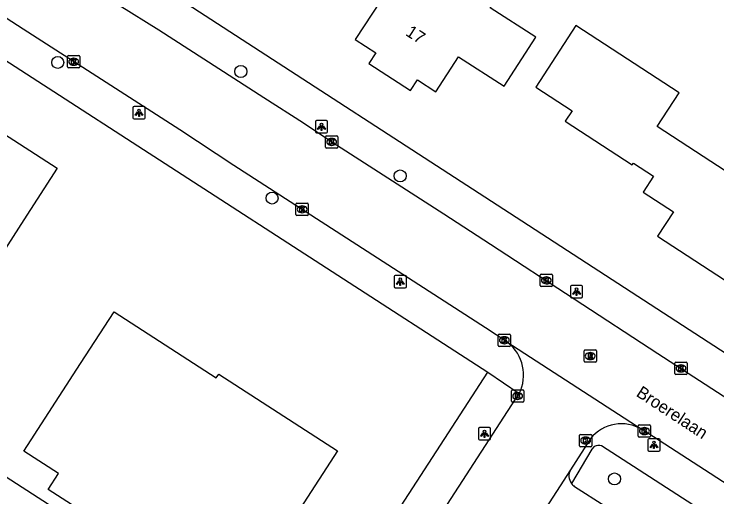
# Model space of a CAD drawing. Extents: x 161141 to 161601, y 381708 to 382245.
# Drawn here: x 161459.7 to 161516.9, y 382033 to 382072.3 of the extents above; entities that cross this region are included whole.
import ezdxf

# ---------------------------------------------------------------- set-up
doc = ezdxf.new("R2010")
doc.units = 0
for name, color, linetype in [('IMGEO_Boom', 7, 'Continuous'), ('IMGEO_Kolk', 7, 'Continuous'), ('IMGEO_Lichtpunt', 7, 'Continuous'), ('IMGEO_Openbare_ruimte_label', 7, 'Continuous'), ('IMGEO_Pand', 7, 'Continuous'), ('IMGEO_Pand_nummerreeks', 7, 'Continuous'), ('IMGEO_Parkeervlak_open', 7, 'Continuous'), ('IMGEO_Rijbaan_lokaal_open', 7, 'Continuous'), ('IMGEO_Rioolput', 7, 'Continuous'), ('IMGEO_Voetpad_open', 7, 'Continuous')]:
    doc.layers.add(name, color=color, linetype=linetype)

msp = doc.modelspace()

# ---------------------------------------------------------------- linework, layer by layer
at = {"layer": 'IMGEO_Boom'}
for centre in [(161463.28, 382068.331), (161478.171, 382067.593), (161491.119, 382059.095), (161480.703, 382057.296), (161508.547, 382034.432)]:
    msp.add_circle(centre, 0.489, dxfattribs=at)
at = {"layer": 'IMGEO_Kolk'}
for p, q in [((161464.08, 382067.96), (161464.08, 382068.812)), ((161464.155, 382068.886), (161465.007, 382068.886)), ((161465.081, 382068.812), (161465.081, 382067.96)), ((161464.591, 382068.106), (161464.566, 382068.106)), ((161464.568, 382068.666), (161464.593, 382068.666)), ((161465.007, 382067.886), (161464.155, 382067.886)), ((161485.053, 382061.434), (161485.053, 382062.286)), ((161485.128, 382062.36), (161485.98, 382062.36)), ((161485.541, 382062.14), (161485.566, 382062.14)), ((161486.054, 382062.286), (161486.054, 382061.434)), ((161485.98, 382061.36), (161485.128, 382061.36)), ((161485.564, 382061.58), (161485.539, 382061.58)), ((161482.65, 382055.951), (161482.65, 382056.803)), ((161482.725, 382056.877), (161483.577, 382056.877)), ((161483.651, 382056.803), (161483.651, 382055.951)), ((161483.138, 382056.657), (161483.163, 382056.657)), ((161483.577, 382055.877), (161482.725, 382055.877)), ((161483.161, 382056.097), (161483.136, 382056.097)), ((161502.507, 382050.171), (161502.507, 382051.023)), ((161502.582, 382051.097), (161503.434, 382051.097)), ((161503.508, 382051.023), (161503.508, 382050.171)), ((161502.995, 382050.877), (161503.02, 382050.877)), ((161503.434, 382050.097), (161502.582, 382050.097)), ((161503.018, 382050.317), (161502.993, 382050.317)), ((161499.094, 382045.296), (161499.094, 382046.148)), ((161499.169, 382046.222), (161500.021, 382046.222)), ((161499.582, 382046.002), (161499.607, 382046.002)), ((161500.095, 382046.148), (161500.095, 382045.296)), ((161499.605, 382045.442), (161499.58, 382045.442)), ((161500.021, 382045.222), (161499.169, 382045.222)), ((161513.457, 382043.004), (161513.457, 382043.856)), ((161513.532, 382043.93), (161514.384, 382043.93)), ((161513.945, 382043.71), (161513.97, 382043.71)), ((161514.458, 382043.856), (161514.458, 382043.004)), ((161513.968, 382043.15), (161513.943, 382043.15)), ((161514.384, 382042.93), (161513.532, 382042.93)), ((161500.17, 382040.761), (161500.17, 382041.613)), ((161500.245, 382041.687), (161501.097, 382041.687)), ((161500.658, 382041.467), (161500.683, 382041.467)), ((161501.171, 382041.613), (161501.171, 382040.761)), ((161501.097, 382040.687), (161500.245, 382040.687)), ((161500.681, 382040.907), (161500.656, 382040.907)), ((161510.478, 382037.909), (161510.478, 382038.761)), ((161510.553, 382038.835), (161511.405, 382038.835)), ((161510.966, 382038.615), (161510.991, 382038.615)), ((161511.479, 382038.761), (161511.479, 382037.909)), ((161505.697, 382037.134), (161505.697, 382037.986)), ((161505.772, 382038.06), (161506.624, 382038.06)), ((161506.185, 382037.84), (161506.21, 382037.84)), ((161506.698, 382037.986), (161506.698, 382037.134)), ((161511.405, 382037.835), (161510.553, 382037.835)), ((161510.989, 382038.055), (161510.964, 382038.055)), ((161506.208, 382037.28), (161506.183, 382037.28)), ((161506.624, 382037.06), (161505.772, 382037.06))]:
    msp.add_line(p, q, dxfattribs=at)
for points in [[(161464.08, 382067.96), (161464.08, 382068.812)], [(161464.155, 382068.886), (161465.007, 382068.886)], [(161465.081, 382068.812), (161465.081, 382067.96)], [(161464.401, 382068.586), (161464.524, 382068.586), (161464.524, 382068.435), (161464.654, 382068.586), (161464.818, 382068.586), (161464.672, 382068.435), (161464.825, 382068.186), (161464.673, 382068.186), (161464.588, 382068.35), (161464.524, 382068.283), (161464.524, 382068.186), (161464.401, 382068.186), (161464.401, 382068.586)], [(161465.007, 382067.886), (161464.155, 382067.886)], [(161485.053, 382061.434), (161485.053, 382062.286)], [(161485.128, 382062.36), (161485.98, 382062.36)], [(161485.374, 382062.06), (161485.497, 382062.06), (161485.497, 382061.909), (161485.627, 382062.06), (161485.791, 382062.06), (161485.645, 382061.909), (161485.798, 382061.66), (161485.646, 382061.66), (161485.561, 382061.824), (161485.497, 382061.757), (161485.497, 382061.66), (161485.374, 382061.66), (161485.374, 382062.06)], [(161486.054, 382062.286), (161486.054, 382061.434)], [(161485.98, 382061.36), (161485.128, 382061.36)], [(161482.65, 382055.951), (161482.65, 382056.803)], [(161482.725, 382056.877), (161483.577, 382056.877)], [(161483.651, 382056.803), (161483.651, 382055.951)], [(161482.971, 382056.577), (161483.094, 382056.577), (161483.094, 382056.426), (161483.224, 382056.577), (161483.388, 382056.577), (161483.242, 382056.426), (161483.395, 382056.177), (161483.243, 382056.177), (161483.158, 382056.341), (161483.094, 382056.274), (161483.094, 382056.177), (161482.971, 382056.177), (161482.971, 382056.577)], [(161483.577, 382055.877), (161482.725, 382055.877)], [(161502.507, 382050.171), (161502.507, 382051.023)], [(161502.582, 382051.097), (161503.434, 382051.097)], [(161503.508, 382051.023), (161503.508, 382050.171)], [(161502.828, 382050.797), (161502.951, 382050.797), (161502.951, 382050.646), (161503.081, 382050.797), (161503.245, 382050.797), (161503.099, 382050.646), (161503.252, 382050.397), (161503.1, 382050.397), (161503.015, 382050.561), (161502.951, 382050.494), (161502.951, 382050.397), (161502.828, 382050.397), (161502.828, 382050.797)], [(161503.434, 382050.097), (161502.582, 382050.097)], [(161499.094, 382045.296), (161499.094, 382046.148)], [(161499.169, 382046.222), (161500.021, 382046.222)], [(161499.415, 382045.922), (161499.538, 382045.922), (161499.538, 382045.771), (161499.668, 382045.922), (161499.832, 382045.922), (161499.686, 382045.771), (161499.839, 382045.522), (161499.687, 382045.522), (161499.602, 382045.686), (161499.538, 382045.619), (161499.538, 382045.522), (161499.415, 382045.522), (161499.415, 382045.922)], [(161500.095, 382046.148), (161500.095, 382045.296)], [(161500.021, 382045.222), (161499.169, 382045.222)], [(161513.457, 382043.004), (161513.457, 382043.856)], [(161513.532, 382043.93), (161514.384, 382043.93)], [(161513.778, 382043.63), (161513.901, 382043.63), (161513.901, 382043.479), (161514.031, 382043.63), (161514.195, 382043.63), (161514.049, 382043.479), (161514.202, 382043.23), (161514.05, 382043.23), (161513.965, 382043.394), (161513.901, 382043.327), (161513.901, 382043.23), (161513.778, 382043.23), (161513.778, 382043.63)], [(161514.458, 382043.856), (161514.458, 382043.004)], [(161514.384, 382042.93), (161513.532, 382042.93)], [(161500.17, 382040.761), (161500.17, 382041.613)], [(161500.245, 382041.687), (161501.097, 382041.687)], [(161500.491, 382041.387), (161500.614, 382041.387), (161500.614, 382041.236), (161500.744, 382041.387), (161500.908, 382041.387), (161500.762, 382041.236), (161500.915, 382040.987), (161500.763, 382040.987), (161500.678, 382041.151), (161500.614, 382041.084), (161500.614, 382040.987), (161500.491, 382040.987), (161500.491, 382041.387)], [(161501.171, 382041.613), (161501.171, 382040.761)], [(161501.097, 382040.687), (161500.245, 382040.687)], [(161510.478, 382037.909), (161510.478, 382038.761)], [(161510.553, 382038.835), (161511.405, 382038.835)], [(161510.799, 382038.535), (161510.922, 382038.535), (161510.922, 382038.384), (161511.052, 382038.535), (161511.216, 382038.535), (161511.07, 382038.384), (161511.223, 382038.135), (161511.071, 382038.135), (161510.986, 382038.299), (161510.922, 382038.232), (161510.922, 382038.135), (161510.799, 382038.135), (161510.799, 382038.535)], [(161511.479, 382038.761), (161511.479, 382037.909)], [(161505.697, 382037.134), (161505.697, 382037.986)], [(161505.772, 382038.06), (161506.624, 382038.06)], [(161506.698, 382037.986), (161506.698, 382037.134)], [(161511.405, 382037.835), (161510.553, 382037.835)], [(161506.018, 382037.76), (161506.141, 382037.76), (161506.141, 382037.609), (161506.271, 382037.76), (161506.435, 382037.76), (161506.289, 382037.609), (161506.442, 382037.36), (161506.29, 382037.36), (161506.205, 382037.524), (161506.141, 382037.457), (161506.141, 382037.36), (161506.018, 382037.36), (161506.018, 382037.76)], [(161506.624, 382037.06), (161505.772, 382037.06)]]:
    msp.add_lwpolyline(points, dxfattribs=at)
for centre, start, end in [((161464.157, 382068.81), 91.552, 178.448), ((161464.157, 382068.81), 91.552, 178.448), ((161465.005, 382068.81), 1.552, 88.448), ((161465.005, 382068.81), 1.552, 88.448), ((161464.157, 382067.962), 181.552, 268.448), ((161464.157, 382067.962), 181.552, 268.448), ((161465.005, 382067.962), 271.552, 358.448), ((161465.005, 382067.962), 271.552, 358.448), ((161485.13, 382062.284), 91.552, 178.448), ((161485.13, 382062.284), 91.552, 178.448), ((161485.978, 382062.284), 1.552, 88.448), ((161485.978, 382062.284), 1.552, 88.448), ((161485.13, 382061.436), 181.552, 268.448), ((161485.13, 382061.436), 181.552, 268.448), ((161485.978, 382061.436), 271.552, 358.448), ((161485.978, 382061.436), 271.552, 358.448), ((161482.727, 382056.801), 91.552, 178.448), ((161482.727, 382056.801), 91.552, 178.448), ((161483.575, 382056.801), 1.552, 88.448), ((161483.575, 382056.801), 1.552, 88.448), ((161482.727, 382055.953), 181.552, 268.448), ((161482.727, 382055.953), 181.552, 268.448), ((161483.575, 382055.953), 271.552, 358.448), ((161483.575, 382055.953), 271.552, 358.448), ((161502.584, 382051.021), 91.552, 178.448), ((161502.584, 382051.021), 91.552, 178.448), ((161503.432, 382051.021), 1.552, 88.448), ((161503.432, 382051.021), 1.552, 88.448), ((161502.584, 382050.173), 181.552, 268.448), ((161502.584, 382050.173), 181.552, 268.448), ((161503.432, 382050.173), 271.552, 358.448), ((161503.432, 382050.173), 271.552, 358.448), ((161499.171, 382046.146), 91.552, 178.448), ((161499.171, 382046.146), 91.552, 178.448), ((161500.019, 382046.146), 1.552, 88.448), ((161500.019, 382046.146), 1.552, 88.448), ((161499.171, 382045.298), 181.552, 268.448), ((161499.171, 382045.298), 181.552, 268.448), ((161500.019, 382045.298), 271.552, 358.448), ((161500.019, 382045.298), 271.552, 358.448), ((161513.534, 382043.854), 91.552, 178.448), ((161513.534, 382043.854), 91.552, 178.448), ((161514.382, 382043.854), 1.552, 88.448), ((161514.382, 382043.854), 1.552, 88.448), ((161513.534, 382043.006), 181.552, 268.448), ((161513.534, 382043.006), 181.552, 268.448), ((161514.382, 382043.006), 271.552, 358.448), ((161514.382, 382043.006), 271.552, 358.448), ((161500.247, 382041.611), 91.552, 178.448), ((161500.247, 382041.611), 91.552, 178.448), ((161501.095, 382041.611), 1.552, 88.448), ((161501.095, 382041.611), 1.552, 88.448), ((161500.247, 382040.763), 181.552, 268.448), ((161500.247, 382040.763), 181.552, 268.448), ((161501.095, 382040.763), 271.552, 358.448), ((161501.095, 382040.763), 271.552, 358.448), ((161510.555, 382038.759), 91.552, 178.448), ((161510.555, 382038.759), 91.552, 178.448), ((161511.403, 382038.759), 1.552, 88.448), ((161511.403, 382038.759), 1.552, 88.448), ((161505.774, 382037.984), 91.552, 178.448), ((161505.774, 382037.984), 91.552, 178.448), ((161506.622, 382037.984), 1.552, 88.448), ((161506.622, 382037.984), 1.552, 88.448), ((161510.555, 382037.911), 181.552, 268.448), ((161510.555, 382037.911), 181.552, 268.448), ((161511.403, 382037.911), 271.552, 358.448), ((161511.403, 382037.911), 271.552, 358.448), ((161505.774, 382037.136), 181.552, 268.448), ((161505.774, 382037.136), 181.552, 268.448), ((161506.622, 382037.136), 271.552, 358.448), ((161506.622, 382037.136), 271.552, 358.448)]:
    msp.add_arc(centre, 0.0765, start, end, dxfattribs=at)
for centre, major_axis, ratio, start_param, end_param in [((161464.567, 382068.386), (-0.387, 0.002), 0.722429, 4.712389, 7.853982), ((161464.592, 382068.386), (-0.39, 0.002), 0.717154, 1.570796, 4.712389), ((161485.54, 382061.86), (-0.387, 0.002), 0.722429, 4.712389, 7.853982), ((161485.565, 382061.86), (-0.39, 0.002), 0.717154, 1.570796, 4.712389), ((161483.137, 382056.377), (-0.387, 0.002), 0.722429, 4.712389, 7.853982), ((161483.162, 382056.377), (-0.39, 0.002), 0.717154, 1.570796, 4.712389), ((161502.994, 382050.597), (-0.387, 0.002), 0.722429, 4.712389, 7.853982), ((161503.019, 382050.597), (-0.39, 0.002), 0.717154, 1.570796, 4.712389), ((161499.581, 382045.722), (-0.387, 0.002), 0.722429, 4.712389, 7.853982), ((161499.606, 382045.722), (-0.39, 0.002), 0.717154, 1.570796, 4.712389), ((161513.944, 382043.43), (-0.387, 0.002), 0.722429, 4.712389, 7.853982), ((161513.969, 382043.43), (-0.39, 0.002), 0.717154, 1.570796, 4.712389), ((161500.657, 382041.187), (-0.387, 0.002), 0.722429, 4.712389, 7.853982), ((161500.682, 382041.187), (-0.39, 0.002), 0.717154, 1.570796, 4.712389), ((161510.965, 382038.335), (-0.387, 0.002), 0.722429, 4.712389, 7.853982), ((161510.99, 382038.335), (-0.39, 0.002), 0.717154, 1.570796, 4.712389), ((161506.184, 382037.56), (-0.387, 0.002), 0.722429, 4.712389, 7.853982), ((161506.209, 382037.56), (-0.39, 0.002), 0.717154, 1.570796, 4.712389)]:
    msp.add_ellipse(centre, major_axis=major_axis, ratio=ratio, start_param=start_param, end_param=end_param, dxfattribs=at)
at = {"layer": 'IMGEO_Lichtpunt'}
for p, q in [((161470.297, 382064.733), (161469.489, 382064.733)), ((161470.297, 382064.733), (161469.489, 382064.733)), ((161469.395, 382064.638), (161469.395, 382063.831)), ((161469.395, 382064.638), (161469.395, 382063.831)), ((161470.391, 382063.831), (161470.391, 382064.638)), ((161470.391, 382063.831), (161470.391, 382064.638)), ((161469.489, 382063.737), (161470.297, 382063.737)), ((161469.489, 382063.737), (161470.297, 382063.737)), ((161485.129, 382063.595), (161484.321, 382063.595)), ((161485.129, 382063.595), (161484.321, 382063.595)), ((161484.227, 382063.5), (161484.227, 382062.693)), ((161484.227, 382063.5), (161484.227, 382062.693)), ((161485.223, 382062.693), (161485.223, 382063.5)), ((161485.223, 382062.693), (161485.223, 382063.5)), ((161484.321, 382062.599), (161485.129, 382062.599)), ((161484.321, 382062.599), (161485.129, 382062.599)), ((161491.534, 382050.992), (161490.726, 382050.992)), ((161491.534, 382050.992), (161490.726, 382050.992)), ((161490.632, 382050.897), (161490.632, 382050.09)), ((161490.632, 382050.897), (161490.632, 382050.09)), ((161491.628, 382050.09), (161491.628, 382050.897)), ((161491.628, 382050.09), (161491.628, 382050.897)), ((161490.726, 382049.996), (161491.534, 382049.996)), ((161490.726, 382049.996), (161491.534, 382049.996)), ((161504.962, 382050.083), (161504.962, 382049.276)), ((161504.962, 382050.083), (161504.962, 382049.276)), ((161505.864, 382050.178), (161505.056, 382050.178)), ((161505.864, 382050.178), (161505.056, 382050.178)), ((161505.958, 382049.276), (161505.958, 382050.083)), ((161505.958, 382049.276), (161505.958, 382050.083)), ((161505.056, 382049.182), (161505.864, 382049.182)), ((161505.056, 382049.182), (161505.864, 382049.182)), ((161497.481, 382038.515), (161497.481, 382037.708)), ((161497.481, 382038.515), (161497.481, 382037.708)), ((161498.383, 382038.61), (161497.575, 382038.61)), ((161498.383, 382038.61), (161497.575, 382038.61)), ((161498.477, 382037.708), (161498.477, 382038.515)), ((161498.477, 382037.708), (161498.477, 382038.515)), ((161497.575, 382037.614), (161498.383, 382037.614)), ((161497.575, 382037.614), (161498.383, 382037.614)), ((161511.254, 382037.606), (161511.254, 382036.799)), ((161511.254, 382037.606), (161511.254, 382036.799)), ((161512.156, 382037.701), (161511.348, 382037.701)), ((161512.156, 382037.701), (161511.348, 382037.701)), ((161512.25, 382036.799), (161512.25, 382037.606)), ((161512.25, 382036.799), (161512.25, 382037.606)), ((161511.348, 382036.705), (161512.156, 382036.705)), ((161511.348, 382036.705), (161512.156, 382036.705))]:
    msp.add_line(p, q, dxfattribs=at)
for points in [[(161469.769, 382064.302), (161469.808, 382064.274), (161469.62, 382064.012), (161469.582, 382064.039), (161469.769, 382064.302)], [(161469.871, 382064.254), (161469.918, 382064.254), (161469.918, 382063.932), (161469.871, 382063.932), (161469.871, 382064.254)], [(161469.981, 382064.274), (161470.019, 382064.301), (161470.206, 382064.039), (161470.167, 382064.011), (161469.981, 382064.274)], [(161484.601, 382063.164), (161484.64, 382063.136), (161484.452, 382062.874), (161484.414, 382062.901), (161484.601, 382063.164)], [(161484.703, 382063.116), (161484.75, 382063.116), (161484.75, 382062.794), (161484.703, 382062.794), (161484.703, 382063.116)], [(161484.813, 382063.136), (161484.851, 382063.163), (161485.038, 382062.901), (161484.999, 382062.873), (161484.813, 382063.136)], [(161491.006, 382050.561), (161491.045, 382050.533), (161490.857, 382050.271), (161490.819, 382050.298), (161491.006, 382050.561)], [(161491.108, 382050.513), (161491.155, 382050.513), (161491.155, 382050.191), (161491.108, 382050.191), (161491.108, 382050.513)], [(161491.218, 382050.533), (161491.256, 382050.56), (161491.443, 382050.298), (161491.404, 382050.27), (161491.218, 382050.533)], [(161505.336, 382049.747), (161505.375, 382049.719), (161505.187, 382049.457), (161505.149, 382049.484), (161505.336, 382049.747)], [(161505.438, 382049.699), (161505.485, 382049.699), (161505.485, 382049.377), (161505.438, 382049.377), (161505.438, 382049.699)], [(161505.548, 382049.719), (161505.586, 382049.746), (161505.773, 382049.484), (161505.734, 382049.456), (161505.548, 382049.719)], [(161497.855, 382038.179), (161497.894, 382038.151), (161497.706, 382037.889), (161497.668, 382037.916), (161497.855, 382038.179)], [(161497.957, 382038.131), (161498.004, 382038.131), (161498.004, 382037.809), (161497.957, 382037.809), (161497.957, 382038.131)], [(161498.067, 382038.151), (161498.105, 382038.178), (161498.292, 382037.916), (161498.253, 382037.888), (161498.067, 382038.151)], [(161511.628, 382037.27), (161511.667, 382037.242), (161511.479, 382036.98), (161511.441, 382037.007), (161511.628, 382037.27)], [(161511.84, 382037.242), (161511.878, 382037.269), (161512.065, 382037.007), (161512.026, 382036.979), (161511.84, 382037.242)], [(161511.73, 382037.222), (161511.777, 382037.222), (161511.777, 382036.9), (161511.73, 382036.9), (161511.73, 382037.222)]]:
    msp.add_lwpolyline(points, dxfattribs=at)
for centre in [(161469.894, 382064.436), (161484.726, 382063.298), (161491.131, 382050.695), (161505.461, 382049.881), (161497.98, 382038.313), (161511.753, 382037.404)]:
    msp.add_circle(centre, 0.0994, dxfattribs=at)
for centre, start, end in [((161469.489, 382064.638), 90, 180), ((161469.489, 382064.638), 90, 180), ((161470.297, 382064.638), 0, 90), ((161470.297, 382064.638), 0, 90), ((161469.489, 382063.831), 180, 270), ((161469.489, 382063.831), 180, 270), ((161470.297, 382063.831), 270, 0), ((161470.297, 382063.831), 270, 360), ((161484.321, 382063.5), 90, 180), ((161484.321, 382063.5), 90, 180), ((161485.129, 382063.5), 0, 90), ((161485.129, 382063.5), 0, 90), ((161484.321, 382062.693), 180, 270), ((161484.321, 382062.693), 180, 270), ((161485.129, 382062.693), 270, 0), ((161485.129, 382062.693), 270, 360), ((161490.726, 382050.897), 90, 180), ((161490.726, 382050.897), 90, 180), ((161491.534, 382050.897), 0, 90), ((161491.534, 382050.897), 0, 90), ((161490.726, 382050.09), 180, 270), ((161490.726, 382050.09), 180, 270), ((161491.534, 382050.09), 270, 0), ((161491.534, 382050.09), 270, 360), ((161505.056, 382050.083), 90, 180), ((161505.056, 382050.083), 90, 180), ((161505.864, 382050.083), 0, 90), ((161505.864, 382050.083), 0, 90), ((161505.056, 382049.276), 180, 270), ((161505.056, 382049.276), 180, 270), ((161505.864, 382049.276), 270, 0), ((161505.864, 382049.276), 270, 360), ((161497.575, 382038.515), 90, 180), ((161497.575, 382038.515), 90, 180), ((161498.383, 382038.515), 0, 90), ((161498.383, 382038.515), 0, 90), ((161497.575, 382037.708), 180, 270), ((161497.575, 382037.708), 180, 270), ((161498.383, 382037.708), 270, 0), ((161498.383, 382037.708), 270, 360), ((161511.348, 382037.606), 90, 180), ((161511.348, 382037.606), 90, 180), ((161512.156, 382037.606), 0, 90), ((161512.156, 382037.606), 0, 90), ((161511.348, 382036.799), 180, 270), ((161511.348, 382036.799), 180, 270), ((161512.156, 382036.799), 270, 0), ((161512.156, 382036.799), 270, 360)]:
    msp.add_arc(centre, 0.0946, start, end, dxfattribs=at)
at = {"layer": 'IMGEO_Pand'}
for points in [[(161500, 382075.192), (161500.497, 382075.96), (161500, 382076.281), (161496.528, 382078.527), (161498.246, 382081.182), (161495.709, 382082.759), (161487.462, 382070.191), (161489.145, 382069.102), (161488.586, 382068.237), (161491.969, 382066.048), (161492.529, 382066.912), (161494.019, 382065.948), (161495.863, 382068.798), (161499.57, 382066.399), (161502.156, 382070.378), (161498.44, 382072.781), (161500, 382075.192)], [(161512.023, 382063.108), (161513.814, 382065.857), (161508.368, 382069.406), (161505.406, 382071.336), (161502.144, 382066.33), (161505.105, 382064.4), (161504.545, 382063.541), (161509.99, 382059.992), (161510.091, 382060.146), (161511.727, 382059.08), (161510.877, 382057.775), (161513.345, 382056.167), (161512.05, 382054.18), (161521.136, 382048.26), (161521.315, 382048.534), (161521.792, 382048.223), (161523.042, 382050.142), (161522.592, 382050.435), (161524.682, 382053.642), (161520.733, 382056.215), (161521.288, 382057.068), (161512.023, 382063.108)], [(161453.071, 382060.334), (161455.786, 382064.533), (161463.24, 382059.714), (161460.525, 382055.515), (161456.345, 382049.049), (161455.075, 382047.085), (161447.621, 382051.906), (161448.89, 382053.869), (161453.071, 382060.334)], [(161465.14, 382043.824), (161467.861, 382048.029), (161476.169, 382042.655), (161476.375, 382042.973), (161486.031, 382036.726), (161463.237, 382001.496), (161453.51, 382007.789)], [(161455.991, 382036.598), (161466.421, 382029.851), (161466.963, 382030.689), (161462.496, 382033.579), (161463.339, 382034.883), (161460.531, 382036.7), (161465.14, 382043.824)]]:
    msp.add_lwpolyline(points, dxfattribs=at)
at = {"layer": 'IMGEO_Parkeervlak_open'}
msp.add_lwpolyline([(161507.761, 382032.211), (161505.308, 382033.806)], dxfattribs=at)
msp.add_arc((161505.897, 382034.678), 1.053, 215.5671, 235.9549, dxfattribs=at)
at = {"layer": 'IMGEO_Rijbaan_lokaal_open'}
for points in [[(161499.796, 382045.589), (161498.051, 382046.741), (161477.592, 382059.945), (161473.195, 382062.836), (161460.477, 382071.037), (161453.542, 382075.54), (161442.527, 382082.644), (161435.549, 382087.163), (161421.669, 382096.147), (161415.306, 382100.289), (161401.761, 382109.008), (161398.574, 382111.058), (161389.569, 382116.981), (161386.277, 382119.018), (161382.915, 382121.211), (161379.746, 382123.279), (161360.833, 382135.554)], [(161385.362, 382126.757), (161388.136, 382124.895), (161391.361, 382122.845), (161399.992, 382117.288), (161403.197, 382115.21), (161416.21, 382106.739), (161420.597, 382103.968), (161426.931, 382099.82), (161440.905, 382090.804), (161444.055, 382088.754), (161453.24, 382082.778), (161460.192, 382078.284), (161467.324, 382073.702), (161468.287, 382073.003), (161471.488, 382070.983), (161480.028, 382065.466), (161483.251, 382063.426), (161485.554, 382061.86), (161494.669, 382055.998), (161498.469, 382053.534), (161512.078, 382044.654), (161521.765, 382038.348), (161525.596, 382035.854)], [(161499.883, 382045.525), (161499.84, 382045.557), (161499.796, 382045.589)], [(161499.796, 382045.589), (161510.796, 382038.454)], [(161464.955, 381985.959), (161500.799, 382041.385)], [(161522.385, 382030.943), (161510.796, 382038.454)], [(161506.592, 382037.718), (161506.547, 382037.659), (161506.503, 382037.599), (161504.966, 382035.175)], [(161504.966, 382035.175), (161491.489, 382014.315)]]:
    msp.add_lwpolyline(points, dxfattribs=at)
for centre, radius, start, end in [((161497.807, 382042.894), 3.351, 333.2345, 51.7176), ((161509.118, 382035.664), 3.256, 58.977, 140.8834)]:
    msp.add_arc(centre, radius, start, end, dxfattribs=at)
at = {"layer": 'IMGEO_Rioolput'}
for p, q in [((161506.073, 382044.011), (161506.073, 382044.863)), ((161506.148, 382044.937), (161507, 382044.937)), ((161506.561, 382044.717), (161506.586, 382044.717)), ((161507.074, 382044.863), (161507.074, 382044.011)), ((161506.584, 382044.157), (161506.559, 382044.157)), ((161507, 382043.937), (161506.148, 382043.937))]:
    msp.add_line(p, q, dxfattribs=at)
for points in [[(161506.073, 382044.011), (161506.073, 382044.863)], [(161506.148, 382044.937), (161507, 382044.937)], [(161507.074, 382044.863), (161507.074, 382044.011)], [(161506.662, 382044.635), (161506.41, 382044.637), (161506.41, 382044.237)], [(161506.41, 382044.237), (161506.534, 382044.237), (161506.534, 382044.399), (161506.545, 382044.399)], [(161506.588, 382044.556), (161506.534, 382044.556), (161506.534, 382044.475)], [(161506.534, 382044.475), (161506.586, 382044.475)], [(161506.592, 382044.37), (161506.663, 382044.237), (161506.803, 382044.237), (161506.738, 382044.363)], [(161507, 382043.937), (161506.148, 382043.937)]]:
    msp.add_lwpolyline(points, dxfattribs=at)
for centre, radius, start, end in [((161506.15, 382044.861), 0.0765, 91.552, 178.448), ((161506.15, 382044.861), 0.0765, 91.552, 178.448), ((161506.998, 382044.861), 0.0765, 1.552, 88.448), ((161506.998, 382044.861), 0.0765, 1.552, 88.448), ((161506.544, 382044.346), 0.0533, 26.0293, 88.6989), ((161506.57, 382044.664), 0.19, 274.7715, 282.9687), ((161506.594, 382044.46), 0.0964, 77.0061, 93.1865), ((161506.608, 382044.517), 0.0378, 276.6634, 79.6772), ((161506.661, 382044.525), 0.109, 350.3612, 89.416), ((161506.659, 382044.525), 0.112, 277.5842, 350.9817), ((161506.643, 382044.31), 0.108, 29.5134, 73.7905), ((161506.15, 382044.013), 0.0765, 181.552, 268.448), ((161506.15, 382044.013), 0.0765, 181.552, 268.448), ((161506.998, 382044.013), 0.0765, 271.552, 358.448), ((161506.998, 382044.013), 0.0765, 271.552, 358.448)]:
    msp.add_arc(centre, radius, start, end, dxfattribs=at)
for centre, major_axis, ratio, start_param, end_param in [((161506.56, 382044.437), (-0.387, 0.002), 0.722429, 4.712389, 7.853982), ((161506.585, 382044.437), (-0.39, 0.002), 0.717154, 1.570796, 4.712389)]:
    msp.add_ellipse(centre, major_axis=major_axis, ratio=ratio, start_param=start_param, end_param=end_param, dxfattribs=at)
at = {"layer": 'IMGEO_Voetpad_open'}
for points in [[(161523.437, 382040.853), (161500, 382056.07), (161450.498, 382088.211), (161408.789, 382114.947), (161389.855, 382127.317), (161365.175, 382143.293), (161365.084, 382143.565)], [(161359.011, 382133.266), (161498.24, 382043.117)], [(161462.38, 381987.777), (161470.3, 382000), (161498.24, 382043.117)], [(161498.24, 382043.117), (161500.799, 382041.385)], [(161506.907, 382037.088), (161506.701, 382036.855), (161505.041, 382034.066)], [(161516.669, 382031.191), (161507.502, 382037.129)]]:
    msp.add_lwpolyline(points, dxfattribs=at)
for centre, radius, start, end in [((161507.263, 382036.263), 0.898, 74.5543, 113.3294), ((161505.9, 382034.681), 1.057, 152.1353, 215.6026)]:
    msp.add_arc(centre, radius, start, end, dxfattribs=at)

# ---------------------------------------------------------------- texts
at = {"layer": 'IMGEO_Openbare_ruimte_label'}
msp.add_text('Broerelaan', height=1, rotation=326.7072, dxfattribs=at).set_placement((161510.238, 382041.228))
at = {"layer": 'IMGEO_Pand_nummerreeks'}
msp.add_text('17', height=1, rotation=327.095, dxfattribs=at).set_placement((161491.492, 382070.584))

doc.saveas('drawing.dxf')
